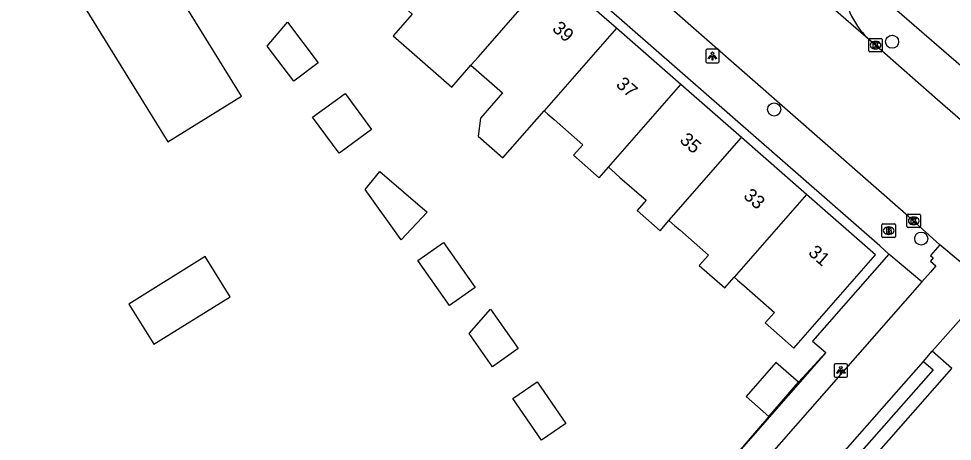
# Model space of a CAD drawing. Extents: x 160026 to 161302, y 384757 to 385701.
# Drawn here: x 160125 to 160194.6, y 385207.7 to 385239.2 of the extents above; entities that cross this region are included whole.
import ezdxf

# ---------------------------------------------------------------- set-up
doc = ezdxf.new("R2010")
doc.units = 0
for name, color, linetype in [('IMGEO_Boom', 7, 'Continuous'), ('IMGEO_Brandkraan', 7, 'Continuous'), ('IMGEO_Haag', 7, 'Continuous'), ('IMGEO_Kolk', 7, 'Continuous'), ('IMGEO_Lichtpunt', 7, 'Continuous'), ('IMGEO_Muur', 7, 'Continuous'), ('IMGEO_Pand', 7, 'Continuous'), ('IMGEO_Pand_nummerreeks', 7, 'Continuous'), ('IMGEO_Rijbaan_lokaal_gesloten', 7, 'Continuous'), ('IMGEO_Rijbaan_lokaal_open', 7, 'Continuous'), ('IMGEO_Voetpad_open', 7, 'Continuous')]:
    doc.layers.add(name, color=color, linetype=linetype)

msp = doc.modelspace()

# ---------------------------------------------------------------- linework, layer by layer
at = {"layer": 'IMGEO_Boom'}
for centre in [(160190.141, 385237.433), (160181.356, 385232.386), (160192.318, 385222.76)]:
    msp.add_circle(centre, 0.489, dxfattribs=at)
at = {"layer": 'IMGEO_Brandkraan'}
for p, q in [((160189.391, 385222.929), (160189.391, 385223.781)), ((160189.466, 385223.855), (160190.318, 385223.855)), ((160189.879, 385223.635), (160189.904, 385223.635)), ((160190.392, 385223.781), (160190.392, 385222.929)), ((160190.318, 385222.855), (160189.466, 385222.855)), ((160189.902, 385223.075), (160189.877, 385223.075))]:
    msp.add_line(p, q, dxfattribs=at)
for points in [[(160189.391, 385222.929), (160189.391, 385223.781)], [(160189.466, 385223.855), (160190.318, 385223.855)], [(160189.739, 385223.555), (160189.739, 385223.155), (160189.952, 385223.155)], [(160189.97, 385223.555), (160189.739, 385223.555)], [(160189.918, 385223.474), (160189.864, 385223.474), (160189.864, 385223.398)], [(160189.864, 385223.398), (160189.917, 385223.398)], [(160189.926, 385223.322), (160189.864, 385223.322), (160189.864, 385223.241)], [(160189.864, 385223.241), (160189.926, 385223.241)], [(160190.392, 385223.781), (160190.392, 385222.929)], [(160190.318, 385222.855), (160189.466, 385222.855)]]:
    msp.add_lwpolyline(points, dxfattribs=at)
for centre, radius, start, end in [((160189.468, 385223.779), 0.0765, 91.55205, 178.44795), ((160189.468, 385223.779), 0.0765, 91.55205, 178.44795), ((160189.919, 385223.436), 0.0379, 267.82845, 90.93552), ((160189.927, 385223.281), 0.0404, 269.87594, 90.50774), ((160189.974, 385223.41), 0.145, 59.4692, 91.53667), ((160189.999, 385223.457), 0.0922, 285.51372, 58.15012), ((160190.004, 385223.265), 0.105, 301.31148, 78.98903), ((160190.316, 385223.779), 0.0765, 1.55205, 88.44795), ((160190.316, 385223.779), 0.0765, 1.55205, 88.44795), ((160189.468, 385222.931), 0.0765, 181.55205, 268.44795), ((160189.468, 385222.931), 0.0765, 181.55205, 268.44795), ((160189.958, 385223.406), 0.251, 268.66757, 293.53466), ((160190.316, 385222.931), 0.0765, 271.55205, 358.44795), ((160190.316, 385222.931), 0.0765, 271.55205, 358.44795)]:
    msp.add_arc(centre, radius, start, end, dxfattribs=at)
for centre, major_axis, ratio, start_param, end_param in [((160189.878, 385223.355), (-0.387, 0.002), 0.722429, 4.712389, 7.853982), ((160189.903, 385223.355), (-0.39, 0.002), 0.717154, 1.570796, 4.712389)]:
    msp.add_ellipse(centre, major_axis=major_axis, ratio=ratio, start_param=start_param, end_param=end_param, dxfattribs=at)
at = {"layer": 'IMGEO_Haag'}
msp.add_lwpolyline([(160192.478, 385213.613), (160193.194, 385212.987), (160179.222, 385197.103), (160179.96, 385196.428), (160194.607, 385213.079), (160193.14, 385214.365)], dxfattribs=at)
at = {"layer": 'IMGEO_Kolk'}
for p, q in [((160188.412, 385236.747), (160188.412, 385237.599)), ((160188.487, 385237.673), (160189.339, 385237.673)), ((160188.9, 385237.453), (160188.925, 385237.453)), ((160189.413, 385237.599), (160189.413, 385236.747)), ((160189.339, 385236.673), (160188.487, 385236.673)), ((160188.923, 385236.893), (160188.898, 385236.893)), ((160191.33, 385224.585), (160192.182, 385224.585)), ((160191.255, 385223.659), (160191.255, 385224.511)), ((160191.743, 385224.365), (160191.768, 385224.365)), ((160192.256, 385224.511), (160192.256, 385223.659)), ((160192.182, 385223.585), (160191.33, 385223.585)), ((160191.766, 385223.805), (160191.741, 385223.805))]:
    msp.add_line(p, q, dxfattribs=at)
for points in [[(160188.412, 385236.747), (160188.412, 385237.599)], [(160188.487, 385237.673), (160189.339, 385237.673)], [(160188.733, 385237.373), (160188.856, 385237.373), (160188.856, 385237.222), (160188.986, 385237.373), (160189.15, 385237.373), (160189.004, 385237.222), (160189.157, 385236.973), (160189.005, 385236.973), (160188.92, 385237.137), (160188.856, 385237.07), (160188.856, 385236.973), (160188.733, 385236.973), (160188.733, 385237.373)], [(160189.413, 385237.599), (160189.413, 385236.747)], [(160189.339, 385236.673), (160188.487, 385236.673)], [(160191.33, 385224.585), (160192.182, 385224.585)], [(160191.255, 385223.659), (160191.255, 385224.511)], [(160191.576, 385224.285), (160191.699, 385224.285), (160191.699, 385224.134), (160191.829, 385224.285), (160191.993, 385224.285), (160191.847, 385224.134), (160192, 385223.885), (160191.848, 385223.885), (160191.763, 385224.049), (160191.699, 385223.982), (160191.699, 385223.885), (160191.576, 385223.885), (160191.576, 385224.285)], [(160192.256, 385224.511), (160192.256, 385223.659)], [(160192.182, 385223.585), (160191.33, 385223.585)]]:
    msp.add_lwpolyline(points, dxfattribs=at)
for centre, start, end in [((160188.489, 385237.597), 91.55205, 178.44795), ((160188.489, 385237.597), 91.55205, 178.44795), ((160189.337, 385237.597), 1.55205, 88.44795), ((160189.337, 385237.597), 1.55205, 88.44795), ((160188.489, 385236.749), 181.55205, 268.44795), ((160188.489, 385236.749), 181.55205, 268.44795), ((160189.337, 385236.749), 271.55205, 358.44795), ((160189.337, 385236.749), 271.55205, 358.44795), ((160191.332, 385224.509), 91.55205, 178.44795), ((160191.332, 385224.509), 91.55205, 178.44795), ((160192.18, 385224.509), 1.55205, 88.44795), ((160192.18, 385224.509), 1.55205, 88.44795), ((160191.332, 385223.661), 181.55205, 268.44795), ((160191.332, 385223.661), 181.55205, 268.44795), ((160192.18, 385223.661), 271.55205, 358.44795), ((160192.18, 385223.661), 271.55205, 358.44795)]:
    msp.add_arc(centre, 0.0765, start, end, dxfattribs=at)
for centre, major_axis, ratio, start_param, end_param in [((160188.899, 385237.173), (-0.387, 0.002), 0.722429, 4.712389, 7.853982), ((160188.924, 385237.173), (-0.39, 0.002), 0.717154, 1.570796, 4.712389), ((160191.742, 385224.085), (-0.387, 0.002), 0.722429, 4.712389, 7.853982), ((160191.767, 385224.085), (-0.39, 0.002), 0.717154, 1.570796, 4.712389)]:
    msp.add_ellipse(centre, major_axis=major_axis, ratio=ratio, start_param=start_param, end_param=end_param, dxfattribs=at)
at = {"layer": 'IMGEO_Lichtpunt'}
for p, q in [((160176.256, 385236.772), (160176.256, 385235.965)), ((160176.256, 385236.772), (160176.256, 385235.965)), ((160177.158, 385236.867), (160176.35, 385236.867)), ((160177.158, 385236.867), (160176.35, 385236.867)), ((160177.252, 385235.965), (160177.252, 385236.772)), ((160177.252, 385235.965), (160177.252, 385236.772)), ((160176.35, 385235.871), (160177.158, 385235.871)), ((160176.35, 385235.871), (160177.158, 385235.871)), ((160185.83, 385213.341), (160185.83, 385212.534)), ((160185.83, 385213.341), (160185.83, 385212.534)), ((160186.732, 385213.436), (160185.924, 385213.436)), ((160186.732, 385213.436), (160185.924, 385213.436)), ((160186.826, 385212.534), (160186.826, 385213.341)), ((160186.826, 385212.534), (160186.826, 385213.341)), ((160185.924, 385212.44), (160186.732, 385212.44)), ((160185.924, 385212.44), (160186.732, 385212.44))]:
    msp.add_line(p, q, dxfattribs=at)
for points in [[(160176.63, 385236.436), (160176.669, 385236.408), (160176.481, 385236.146), (160176.443, 385236.173), (160176.63, 385236.436)], [(160176.842, 385236.408), (160176.88, 385236.435), (160177.067, 385236.173), (160177.028, 385236.145), (160176.842, 385236.408)], [(160176.732, 385236.388), (160176.779, 385236.388), (160176.779, 385236.066), (160176.732, 385236.066), (160176.732, 385236.388)], [(160186.204, 385213.005), (160186.243, 385212.977), (160186.055, 385212.715), (160186.017, 385212.742), (160186.204, 385213.005)], [(160186.306, 385212.957), (160186.353, 385212.957), (160186.353, 385212.635), (160186.306, 385212.635), (160186.306, 385212.957)], [(160186.416, 385212.977), (160186.454, 385213.004), (160186.641, 385212.742), (160186.602, 385212.714), (160186.416, 385212.977)]]:
    msp.add_lwpolyline(points, dxfattribs=at)
for centre in [(160176.755, 385236.57), (160186.329, 385213.139)]:
    msp.add_circle(centre, 0.0994, dxfattribs=at)
for centre, start, end in [((160176.35, 385236.772), 90, 180), ((160176.35, 385236.772), 90, 180), ((160177.158, 385236.772), 0, 90), ((160177.158, 385236.772), 0, 90), ((160176.35, 385235.965), 180, 270), ((160176.35, 385235.965), 180, 270), ((160177.158, 385235.965), 270, 0), ((160177.158, 385235.965), 270, 360), ((160185.924, 385213.341), 90, 180), ((160185.924, 385213.341), 90, 180), ((160186.732, 385213.341), 0, 90), ((160186.732, 385213.341), 0, 90), ((160185.924, 385212.534), 180, 270), ((160185.924, 385212.534), 180, 270), ((160186.732, 385212.534), 270, 0), ((160186.732, 385212.534), 270, 360)]:
    msp.add_arc(centre, 0.0946, start, end, dxfattribs=at)
at = {"layer": 'IMGEO_Muur'}
msp.add_lwpolyline([(160185.196, 385214.261), (160176.958, 385204.861)], dxfattribs=at)
at = {"layer": 'IMGEO_Pand'}
for points in [[(160132.337, 385248.492), (160130.12, 385252.088), (160124.615, 385248.695), (160126.832, 385245.099), (160136.156, 385229.972), (160141.661, 385233.366), (160135.133, 385243.956), (160132.337, 385248.492)], [(160158.756, 385235.681), (160159.314, 385236.319), (160164.819, 385242.612)], [(160169.594, 385238.436), (160164.819, 385242.612)], [(160154.1, 385239.727), (160154.373, 385239.488), (160152.967, 385237.879), (160157.336, 385234.058), (160158.756, 385235.681)], [(160145.084, 385238.878), (160147.365, 385235.871), (160145.549, 385234.493), (160143.577, 385237.094), (160145.084, 385238.878)], [(160169.594, 385238.436), (160164.207, 385232.276)], [(160174.391, 385234.239), (160169.594, 385238.436)], [(160158.756, 385235.681), (160161.109, 385233.623), (160159.467, 385231.735), (160159.284, 385230.398), (160161.143, 385228.772), (160164.207, 385232.276)], [(160168.999, 385228.073), (160174.391, 385234.239)], [(160178.912, 385230.286), (160174.391, 385234.239)], [(160149.372, 385233.579), (160151.339, 385230.897), (160149.072, 385229.235), (160148.925, 385229.127), (160146.959, 385231.81), (160149.372, 385233.579)], [(160164.207, 385232.276), (160164.484, 385232.034), (160164.95, 385231.626), (160167.094, 385229.751), (160166.409, 385228.968), (160168.32, 385227.297), (160168.999, 385228.073)], [(160173.511, 385224.11), (160178.912, 385230.286)], [(160183.766, 385226.04), (160178.912, 385230.286)], [(160168.999, 385228.073), (160169.22, 385227.88), (160169.853, 385227.326), (160171.805, 385225.619), (160171.133, 385224.851), (160172.848, 385223.352), (160173.511, 385224.11)], [(160151.969, 385227.75), (160155.491, 385224.742), (160153.56, 385222.658), (160150.867, 385226.42), (160151.969, 385227.75)], [(160183.766, 385226.04), (160178.379, 385219.88)], [(160178.379, 385219.88), (160178.623, 385219.667), (160179.095, 385219.254), (160181.368, 385217.266), (160180.678, 385216.477), (160182.827, 385214.597), (160188.904, 385221.546), (160183.766, 385226.04)], [(160173.511, 385224.11), (160173.956, 385223.72), (160174.318, 385223.403), (160176.457, 385221.532), (160175.772, 385220.748), (160177.679, 385219.08), (160178.379, 385219.88)], [(160156.721, 385222.472), (160159.074, 385219.128), (160157.151, 385217.775), (160154.798, 385221.119), (160156.721, 385222.472)], [(160133.269, 385217.881), (160135.128, 385214.895), (160140.81, 385218.431), (160138.951, 385221.418), (160133.269, 385217.881)], [(160160.212, 385217.51), (160162.284, 385214.565), (160160.361, 385213.212), (160158.621, 385215.685), (160160.212, 385217.51)], [(160183.18, 385212.051), (160181.48, 385213.538), (160179.256, 385210.996), (160180.957, 385209.509)], [(160163.688, 385212.08), (160165.824, 385208.983), (160164.023, 385207.74), (160161.887, 385210.837), (160163.688, 385212.08)], [(160180.957, 385209.509), (160183.18, 385212.051)]]:
    msp.add_lwpolyline(points, dxfattribs=at)
at = {"layer": 'IMGEO_Rijbaan_lokaal_gesloten'}
for points in [[(160193.713, 385222.293), (160191.374, 385224.407), (160173.333, 385240.195), (160162.08, 385250), (160161.735, 385250.3)], [(160175.917, 385248.467), (160188.548, 385237.492)], [(160188.548, 385237.492), (160193.527, 385233.12), (160198.24, 385229.032), (160202.411, 385225.421), (160206.637, 385221.839)], [(160198.237, 385218.491), (160193.713, 385222.293)]]:
    msp.add_lwpolyline(points, dxfattribs=at)
at = {"layer": 'IMGEO_Rijbaan_lokaal_open'}
for points in [[(160193.713, 385222.293), (160192.998, 385221.497), (160193.214, 385221.318), (160193.018, 385221.086), (160193.416, 385220.739), (160192.997, 385220.266), (160192.368, 385219.549)], [(160192.368, 385219.549), (160174.595, 385199.292)], [(160193.14, 385214.365), (160195.298, 385216.818)], [(160192.478, 385213.613), (160193.14, 385214.365)], [(160178.049, 385197.213), (160192.478, 385213.613)]]:
    msp.add_lwpolyline(points, dxfattribs=at)
msp.add_arc((160192.494, 385241.985), 5.98, 183.61614, 228.70936, dxfattribs=at)
at = {"layer": 'IMGEO_Voetpad_open'}
for points in [[(160189.897, 385221.607), (160189.22, 385222.221), (160157.452, 385250), (160136.269, 385268.493)], [(160189.941, 385240.261), (160210.397, 385222.565), (160223.089, 385212.512)], [(160189.897, 385221.607), (160184.205, 385215.122), (160185.196, 385214.261), (160183.18, 385212.051)], [(160192.368, 385219.549), (160189.897, 385221.607)], [(160180.957, 385209.509), (160176.958, 385204.861), (160169.801, 385196.926), (160170.217, 385196.478), (160164.623, 385190.524), (160161.939, 385188.142), (160161.174, 385187.582), (160153.331, 385182.894), (160147.881, 385179.757), (160148.28, 385178.965), (160139.009, 385173.66), (160125.347, 385165.848)]]:
    msp.add_lwpolyline(points, dxfattribs=at)

# ---------------------------------------------------------------- texts
at = {"layer": 'IMGEO_Pand_nummerreeks'}
for s, p in [('39', (160164.75, 385238.315)), ('37', (160169.5, 385234.161)), ('35', (160174.25, 385230.007)), ('33', (160178.999, 385225.853)), ('31', (160183.834, 385221.623))]:
    msp.add_text(s, height=1, rotation=318.82725, dxfattribs=at).set_placement(p)

doc.saveas('drawing.dxf')
